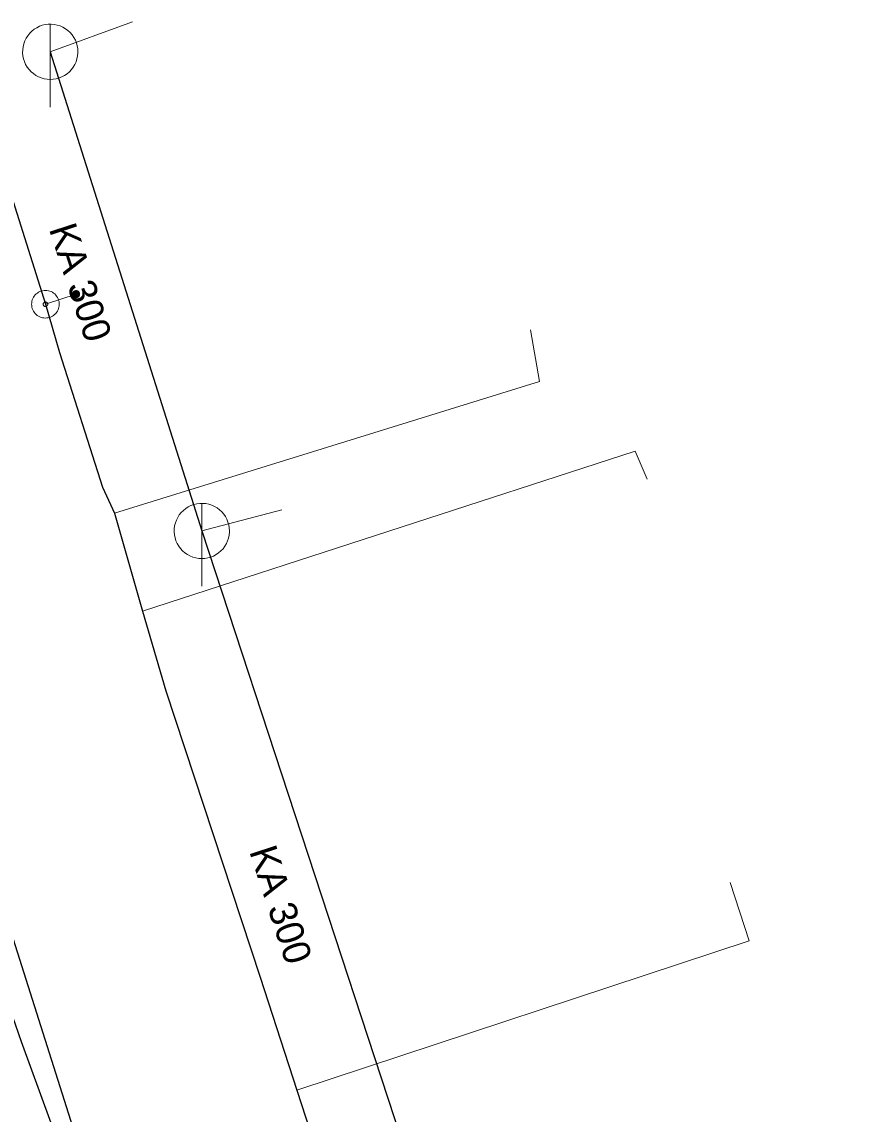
# Model space of a CAD drawing. Extents: x -807203 to -805207, y -993656 to -992505.
# Drawn here: x -807103.6 to -807072.84, y -993130.79 to -993091.29 of the extents above; entities that cross this region are included whole.
import ezdxf

# ---------------------------------------------------------------- set-up
doc = ezdxf.new("R2010")
doc.units = 0
doc.header["$LTSCALE"] = 0.4
for name, color, linetype, lineweight in [('1', 7, 'Continuous', 13), ('11', 7, 'Continuous', 13), ('13', 7, 'Continuous', 13), ('14', 7, 'Continuous', 25), ('17', 7, 'Continuous', 25), ('22', 7, 'Continuous', 13), ('47', 7, 'Continuous', 13), ('9', 7, 'Continuous', 13)]:
    doc.layers.add(name, color=color, linetype=linetype, lineweight=lineweight)

msp = doc.modelspace()

# ---------------------------------------------------------------- linework, layer by layer
at = {"layer": '11'}
for p, q in [((-807099.6, -993091.287), (-807102.57, -993092.37)), ((-807094.193, -993108.938), (-807097.09, -993109.699))]:
    msp.add_line(p, q, dxfattribs=at)
at = {"layer": '13'}
for points in [[(-807100.244, -993109.059), (-807084.873, -993104.294), (-807085.199, -993102.421)], [(-807099.235, -993112.603), (-807081.415, -993106.811), (-807080.985, -993107.831)], [(-807093.654, -993129.924), (-807077.287, -993124.524), (-807077.982, -993122.408)]]:
    msp.add_lwpolyline(points, dxfattribs=at)
at = {"layer": '14'}
for p, q in [((-807102.57, -993092.37), (-807097.09, -993109.699)), ((-807097.09, -993109.699), (-807088.03, -993137.32))]:
    msp.add_line(p, q, dxfattribs=at)
at = {"layer": '14', "lineweight": 13}
msp.add_line((-807102.744, -993101.5), (-807101.634, -993101.133), dxfattribs=at)
at = {"layer": '14'}
msp.add_lwpolyline([(-807110.309, -993104.32), (-807109.321, -993107.433), (-807106.151, -993117.421), (-807099.532, -993138.273), (-807098.539, -993141.399)], dxfattribs=at)
at = {"layer": '17'}
msp.add_line((-807104.484, -993096.025), (-807102.744, -993101.5), dxfattribs=at)
for points in [[(-807102.744, -993101.5), (-807102.241, -993103.247), (-807100.675, -993108.116), (-807100.243, -993109.059), (-807099.234, -993112.603), (-807098.39, -993115.482), (-807094.98, -993125.833), (-807093.653, -993129.923), (-807088.842, -993144.708), (-807087.517, -993148.8), (-807087.074, -993150.114), (-807085.368, -993155.225), (-807083.942, -993159.686), (-807072.827, -993193.081), (-807070.855, -993198.727), (-807058.136, -993236.557), (-807055.798, -993243.556), (-807050.671, -993258.89), (-807046.204, -993272.388), (-807040.605, -993289.576), (-807026.284, -993334.262)], [(-807106.216, -993120.722), (-807103.627, -993128.16), (-807102.219, -993132), (-807096.589, -993150.385), (-807096.195, -993151.629), (-807092.921, -993162.153), (-807079.791, -993202.059), (-807064.89, -993246.39), (-807059.596, -993262.052), (-807055.035, -993275.397), (-807053.806, -993278.989)]]:
    msp.add_lwpolyline(points, dxfattribs=at)
at = {"layer": '22'}
for p, q in [((-807102.57, -993094.37), (-807102.569, -993091.37)), ((-807097.09, -993111.699), (-807097.089, -993108.699))]:
    msp.add_line(p, q, dxfattribs=at)
for points in [[(-807101.57, -993092.37), (-807101.575, -993092.261), (-807101.593, -993092.153), (-807101.623, -993092.047), (-807101.663, -993091.946), (-807101.715, -993091.849), (-807101.777, -993091.759), (-807101.849, -993091.676), (-807101.929, -993091.602), (-807102.017, -993091.536), (-807102.111, -993091.481), (-807102.211, -993091.436), (-807102.316, -993091.403), (-807102.423, -993091.381), (-807102.532, -993091.371), (-807102.642, -993091.373), (-807102.75, -993091.387), (-807102.857, -993091.412), (-807102.96, -993091.449), (-807103.058, -993091.498), (-807103.15, -993091.556), (-807103.236, -993091.625), (-807103.313, -993091.702), (-807103.382, -993091.788), (-807103.441, -993091.88), (-807103.489, -993091.978), (-807103.526, -993092.081), (-807103.552, -993092.188), (-807103.566, -993092.296), (-807103.569, -993092.406), (-807103.559, -993092.515), (-807103.538, -993092.622), (-807103.504, -993092.726), (-807103.46, -993092.826), (-807103.405, -993092.921), (-807103.339, -993093.009), (-807103.265, -993093.089), (-807103.182, -993093.161), (-807103.092, -993093.223), (-807102.996, -993093.275), (-807102.894, -993093.316), (-807102.789, -993093.346), (-807102.681, -993093.364), (-807102.571, -993093.37), (-807102.462, -993093.364), (-807102.354, -993093.346), (-807102.249, -993093.317), (-807102.147, -993093.276), (-807102.05, -993093.224), (-807101.96, -993093.162), (-807101.877, -993093.091), (-807101.802, -993093.011), (-807101.737, -993092.923), (-807101.681, -993092.829), (-807101.637, -993092.729), (-807101.603, -993092.625), (-807101.581, -993092.517), (-807101.571, -993092.408)], [(-807096.09, -993109.699), (-807096.095, -993109.59), (-807096.113, -993109.482), (-807096.143, -993109.376), (-807096.183, -993109.275), (-807096.235, -993109.178), (-807096.297, -993109.088), (-807096.369, -993109.005), (-807096.449, -993108.931), (-807096.537, -993108.865), (-807096.631, -993108.81), (-807096.731, -993108.765), (-807096.836, -993108.732), (-807096.943, -993108.71), (-807097.052, -993108.7), (-807097.162, -993108.702), (-807097.27, -993108.716), (-807097.377, -993108.741), (-807097.48, -993108.778), (-807097.578, -993108.827), (-807097.67, -993108.885), (-807097.756, -993108.954), (-807097.833, -993109.031), (-807097.902, -993109.117), (-807097.961, -993109.209), (-807098.009, -993109.307), (-807098.046, -993109.41), (-807098.072, -993109.517), (-807098.086, -993109.625), (-807098.089, -993109.735), (-807098.079, -993109.844), (-807098.058, -993109.951), (-807098.024, -993110.055), (-807097.98, -993110.155), (-807097.925, -993110.25), (-807097.859, -993110.338), (-807097.785, -993110.418), (-807097.702, -993110.49), (-807097.612, -993110.552), (-807097.516, -993110.604), (-807097.414, -993110.645), (-807097.309, -993110.675), (-807097.201, -993110.693), (-807097.091, -993110.699), (-807096.982, -993110.693), (-807096.874, -993110.675), (-807096.769, -993110.646), (-807096.667, -993110.605), (-807096.57, -993110.553), (-807096.48, -993110.491), (-807096.397, -993110.42), (-807096.322, -993110.34), (-807096.257, -993110.252), (-807096.201, -993110.158), (-807096.157, -993110.058), (-807096.123, -993109.954), (-807096.101, -993109.846), (-807096.091, -993109.737)]]:
    msp.add_lwpolyline(points, close=True, dxfattribs=at)
at = {"layer": '47'}
for points in [[(-807102.591, -993101.976), (-807102.542, -993101.957), (-807102.495, -993101.933), (-807102.452, -993101.905), (-807102.411, -993101.873), (-807102.373, -993101.835), (-807102.34, -993101.794), (-807102.312, -993101.751), (-807102.288, -993101.704), (-807102.269, -993101.656), (-807102.255, -993101.605), (-807102.246, -993101.553), (-807102.244, -993101.501), (-807102.246, -993101.449), (-807102.254, -993101.397), (-807102.267, -993101.347), (-807102.286, -993101.298), (-807102.31, -993101.251), (-807102.339, -993101.207), (-807102.37, -993101.167), (-807102.408, -993101.129), (-807102.449, -993101.096), (-807102.493, -993101.067), (-807102.539, -993101.043), (-807102.587, -993101.024), (-807102.638, -993101.011), (-807102.69, -993101.002), (-807102.742, -993100.999), (-807102.794, -993101.002), (-807102.846, -993101.01), (-807102.896, -993101.023), (-807102.945, -993101.042), (-807102.992, -993101.066), (-807103.036, -993101.094), (-807103.076, -993101.126), (-807103.114, -993101.164), (-807103.147, -993101.204), (-807103.176, -993101.248), (-807103.2, -993101.294), (-807103.219, -993101.343), (-807103.232, -993101.394), (-807103.241, -993101.446), (-807103.244, -993101.497), (-807103.241, -993101.55), (-807103.233, -993101.602), (-807103.22, -993101.652), (-807103.201, -993101.701), (-807103.177, -993101.748), (-807103.15, -993101.792), (-807103.117, -993101.832), (-807103.079, -993101.87), (-807103.039, -993101.903), (-807102.996, -993101.931), (-807102.949, -993101.955), (-807102.9, -993101.974), (-807102.849, -993101.988), (-807102.797, -993101.997), (-807102.746, -993101.999), (-807102.693, -993101.997), (-807102.641, -993101.989)], [(-807102.718, -993101.578), (-807102.71, -993101.575), (-807102.703, -993101.57), (-807102.696, -993101.566), (-807102.689, -993101.561), (-807102.683, -993101.555), (-807102.678, -993101.548), (-807102.672, -993101.541), (-807102.669, -993101.533), (-807102.666, -993101.525), (-807102.663, -993101.517), (-807102.662, -993101.508), (-807102.662, -993101.499), (-807102.662, -993101.491), (-807102.663, -993101.483), (-807102.665, -993101.474), (-807102.668, -993101.466), (-807102.673, -993101.459), (-807102.677, -993101.452), (-807102.682, -993101.445), (-807102.688, -993101.439), (-807102.695, -993101.434), (-807102.702, -993101.428), (-807102.71, -993101.425), (-807102.718, -993101.421), (-807102.726, -993101.419), (-807102.735, -993101.418), (-807102.744, -993101.418), (-807102.752, -993101.418), (-807102.76, -993101.419), (-807102.769, -993101.421), (-807102.777, -993101.424), (-807102.784, -993101.429), (-807102.791, -993101.433), (-807102.798, -993101.438), (-807102.804, -993101.444), (-807102.81, -993101.45), (-807102.815, -993101.458), (-807102.818, -993101.466), (-807102.822, -993101.474), (-807102.824, -993101.482), (-807102.825, -993101.491), (-807102.825, -993101.5), (-807102.825, -993101.508), (-807102.824, -993101.516), (-807102.822, -993101.525), (-807102.819, -993101.533), (-807102.814, -993101.54), (-807102.81, -993101.547), (-807102.805, -993101.554), (-807102.799, -993101.56), (-807102.793, -993101.566), (-807102.785, -993101.571), (-807102.777, -993101.574), (-807102.769, -993101.577), (-807102.761, -993101.58), (-807102.752, -993101.581), (-807102.743, -993101.581), (-807102.735, -993101.581), (-807102.727, -993101.58)]]:
    msp.add_lwpolyline(points, close=True, dxfattribs=at)
at = {"layer": '9'}
for points in [[(-807101.76, -993101.133), (-807101.76, -993101.146), (-807101.757, -993101.159), (-807101.755, -993101.172), (-807101.75, -993101.184), (-807101.744, -993101.196), (-807101.737, -993101.207), (-807101.728, -993101.217), (-807101.718, -993101.227), (-807101.708, -993101.235), (-807101.698, -993101.242), (-807101.686, -993101.248), (-807101.674, -993101.253), (-807101.661, -993101.256), (-807101.647, -993101.258), (-807101.635, -993101.26), (-807101.622, -993101.259), (-807101.608, -993101.257), (-807101.596, -993101.254), (-807101.583, -993101.249), (-807101.571, -993101.243), (-807101.561, -993101.236), (-807101.551, -993101.228), (-807101.541, -993101.218), (-807101.532, -993101.208), (-807101.526, -993101.197), (-807101.52, -993101.185), (-807101.515, -993101.173), (-807101.512, -993101.16), (-807101.51, -993101.147), (-807101.507, -993101.134), (-807101.509, -993101.121), (-807101.511, -993101.108), (-807101.514, -993101.095), (-807101.519, -993101.083), (-807101.524, -993101.071), (-807101.532, -993101.06), (-807101.539, -993101.05), (-807101.549, -993101.04), (-807101.559, -993101.032), (-807101.571, -993101.025), (-807101.583, -993101.019), (-807101.595, -993101.014), (-807101.608, -993101.011), (-807101.62, -993101.009), (-807101.634, -993101.008), (-807101.647, -993101.008), (-807101.659, -993101.01), (-807101.673, -993101.013), (-807101.684, -993101.018), (-807101.696, -993101.024), (-807101.708, -993101.031), (-807101.718, -993101.039), (-807101.728, -993101.049), (-807101.735, -993101.059), (-807101.743, -993101.07), (-807101.749, -993101.082), (-807101.754, -993101.094), (-807101.757, -993101.107), (-807101.759, -993101.12)], [(-807101.74, -993101.133), (-807101.74, -993101.144), (-807101.739, -993101.155), (-807101.735, -993101.166), (-807101.732, -993101.176), (-807101.727, -993101.186), (-807101.721, -993101.195), (-807101.713, -993101.204), (-807101.706, -993101.212), (-807101.696, -993101.219), (-807101.688, -993101.225), (-807101.678, -993101.23), (-807101.668, -993101.234), (-807101.657, -993101.237), (-807101.646, -993101.24), (-807101.635, -993101.24), (-807101.624, -993101.24), (-807101.613, -993101.238), (-807101.602, -993101.235), (-807101.592, -993101.231), (-807101.581, -993101.226), (-807101.573, -993101.22), (-807101.564, -993101.213), (-807101.556, -993101.205), (-807101.549, -993101.196), (-807101.543, -993101.187), (-807101.538, -993101.177), (-807101.534, -993101.167), (-807101.531, -993101.156), (-807101.529, -993101.145), (-807101.527, -993101.134), (-807101.527, -993101.123), (-807101.529, -993101.112), (-807101.532, -993101.101), (-807101.537, -993101.091), (-807101.542, -993101.081), (-807101.548, -993101.072), (-807101.554, -993101.063), (-807101.563, -993101.055), (-807101.571, -993101.048), (-807101.581, -993101.042), (-807101.591, -993101.037), (-807101.6, -993101.033), (-807101.612, -993101.03), (-807101.622, -993101.028), (-807101.634, -993101.028), (-807101.645, -993101.027), (-807101.656, -993101.029), (-807101.667, -993101.032), (-807101.676, -993101.036), (-807101.686, -993101.041), (-807101.696, -993101.047), (-807101.705, -993101.054), (-807101.713, -993101.062), (-807101.72, -993101.071), (-807101.725, -993101.08), (-807101.73, -993101.09), (-807101.735, -993101.1), (-807101.738, -993101.111), (-807101.74, -993101.122)], [(-807101.721, -993101.133), (-807101.721, -993101.142), (-807101.72, -993101.151), (-807101.717, -993101.16), (-807101.713, -993101.168), (-807101.71, -993101.176), (-807101.705, -993101.184), (-807101.698, -993101.191), (-807101.693, -993101.197), (-807101.686, -993101.203), (-807101.678, -993101.208), (-807101.669, -993101.212), (-807101.662, -993101.215), (-807101.652, -993101.218), (-807101.644, -993101.219), (-807101.635, -993101.221), (-807101.625, -993101.22), (-807101.617, -993101.219), (-807101.608, -993101.216), (-807101.6, -993101.213), (-807101.592, -993101.209), (-807101.583, -993101.204), (-807101.576, -993101.198), (-807101.571, -993101.192), (-807101.565, -993101.185), (-807101.559, -993101.177), (-807101.556, -993101.169), (-807101.553, -993101.161), (-807101.549, -993101.152), (-807101.549, -993101.143), (-807101.546, -993101.134), (-807101.548, -993101.125), (-807101.549, -993101.116), (-807101.551, -993101.107), (-807101.554, -993101.099), (-807101.559, -993101.091), (-807101.564, -993101.083), (-807101.57, -993101.076), (-807101.576, -993101.07), (-807101.583, -993101.064), (-807101.591, -993101.059), (-807101.598, -993101.055), (-807101.607, -993101.052), (-807101.615, -993101.049), (-807101.625, -993101.048), (-807101.634, -993101.047), (-807101.642, -993101.047), (-807101.652, -993101.048), (-807101.661, -993101.051), (-807101.669, -993101.054), (-807101.676, -993101.058), (-807101.684, -993101.063), (-807101.691, -993101.069), (-807101.698, -993101.075), (-807101.703, -993101.082), (-807101.708, -993101.09), (-807101.713, -993101.098), (-807101.716, -993101.106), (-807101.718, -993101.115), (-807101.72, -993101.124)], [(-807101.701, -993101.133), (-807101.701, -993101.14), (-807101.7, -993101.147), (-807101.698, -993101.154), (-807101.696, -993101.16), (-807101.693, -993101.166), (-807101.689, -993101.172), (-807101.684, -993101.178), (-807101.679, -993101.183), (-807101.674, -993101.187), (-807101.668, -993101.191), (-807101.662, -993101.194), (-807101.656, -993101.197), (-807101.649, -993101.198), (-807101.642, -993101.201), (-807101.635, -993101.201), (-807101.627, -993101.201), (-807101.62, -993101.199), (-807101.614, -993101.198), (-807101.608, -993101.195), (-807101.6, -993101.192), (-807101.596, -993101.188), (-807101.59, -993101.184), (-807101.585, -993101.179), (-807101.581, -993101.173), (-807101.576, -993101.167), (-807101.573, -993101.161), (-807101.571, -993101.155), (-807101.569, -993101.148), (-807101.568, -993101.141), (-807101.566, -993101.134), (-807101.566, -993101.127), (-807101.568, -993101.12), (-807101.57, -993101.113), (-807101.573, -993101.107), (-807101.576, -993101.1), (-807101.58, -993101.095), (-807101.583, -993101.089), (-807101.588, -993101.084), (-807101.595, -993101.08), (-807101.6, -993101.076), (-807101.607, -993101.073), (-807101.613, -993101.07), (-807101.62, -993101.068), (-807101.627, -993101.067), (-807101.634, -993101.067), (-807101.641, -993101.067), (-807101.647, -993101.067), (-807101.654, -993101.069), (-807101.661, -993101.072), (-807101.667, -993101.075), (-807101.673, -993101.079), (-807101.679, -993101.083), (-807101.684, -993101.088), (-807101.688, -993101.094), (-807101.691, -993101.099), (-807101.695, -993101.106), (-807101.698, -993101.112), (-807101.698, -993101.119), (-807101.701, -993101.126)], [(-807101.681, -993101.133), (-807101.681, -993101.138), (-807101.681, -993101.143), (-807101.679, -993101.148), (-807101.678, -993101.152), (-807101.676, -993101.157), (-807101.673, -993101.161), (-807101.669, -993101.164), (-807101.666, -993101.168), (-807101.663, -993101.171), (-807101.659, -993101.174), (-807101.654, -993101.176), (-807101.649, -993101.178), (-807101.645, -993101.179), (-807101.64, -993101.181), (-807101.635, -993101.181), (-807101.63, -993101.181), (-807101.625, -993101.18), (-807101.62, -993101.179), (-807101.615, -993101.177), (-807101.61, -993101.175), (-807101.607, -993101.172), (-807101.603, -993101.169), (-807101.6, -993101.165), (-807101.597, -993101.162), (-807101.593, -993101.158), (-807101.592, -993101.153), (-807101.59, -993101.149), (-807101.588, -993101.144), (-807101.588, -993101.139), (-807101.587, -993101.134), (-807101.587, -993101.129), (-807101.588, -993101.124), (-807101.588, -993101.119), (-807101.591, -993101.115), (-807101.593, -993101.11), (-807101.596, -993101.106), (-807101.598, -993101.102), (-807101.602, -993101.099), (-807101.605, -993101.096), (-807101.61, -993101.093), (-807101.615, -993101.091), (-807101.619, -993101.089), (-807101.624, -993101.088), (-807101.629, -993101.087), (-807101.634, -993101.087), (-807101.639, -993101.087), (-807101.644, -993101.088), (-807101.649, -993101.088), (-807101.652, -993101.09), (-807101.657, -993101.092), (-807101.662, -993101.095), (-807101.664, -993101.098), (-807101.669, -993101.101), (-807101.671, -993101.105), (-807101.674, -993101.109), (-807101.676, -993101.114), (-807101.679, -993101.118), (-807101.679, -993101.123), (-807101.681, -993101.128)], [(-807101.661, -993101.133), (-807101.661, -993101.136), (-807101.662, -993101.139), (-807101.661, -993101.141), (-807101.659, -993101.144), (-807101.659, -993101.147), (-807101.657, -993101.149), (-807101.654, -993101.151), (-807101.652, -993101.153), (-807101.651, -993101.155), (-807101.649, -993101.157), (-807101.646, -993101.159), (-807101.642, -993101.16), (-807101.641, -993101.16), (-807101.637, -993101.161), (-807101.635, -993101.161), (-807101.632, -993101.161), (-807101.629, -993101.161), (-807101.625, -993101.16), (-807101.624, -993101.159), (-807101.62, -993101.158), (-807101.619, -993101.156), (-807101.615, -993101.154), (-807101.614, -993101.152), (-807101.613, -993101.15), (-807101.61, -993101.148), (-807101.61, -993101.145), (-807101.608, -993101.142), (-807101.608, -993101.14), (-807101.607, -993101.137), (-807101.605, -993101.134), (-807101.607, -993101.131), (-807101.607, -993101.128), (-807101.608, -993101.125), (-807101.608, -993101.123), (-807101.61, -993101.12), (-807101.612, -993101.118), (-807101.613, -993101.115), (-807101.615, -993101.113), (-807101.618, -993101.112), (-807101.62, -993101.11), (-807101.622, -993101.109), (-807101.625, -993101.108), (-807101.627, -993101.107), (-807101.63, -993101.107), (-807101.634, -993101.106), (-807101.637, -993101.107), (-807101.64, -993101.106), (-807101.642, -993101.108), (-807101.645, -993101.108), (-807101.647, -993101.109), (-807101.649, -993101.111), (-807101.652, -993101.112), (-807101.654, -993101.114), (-807101.656, -993101.117), (-807101.657, -993101.119), (-807101.659, -993101.122), (-807101.659, -993101.124), (-807101.661, -993101.127), (-807101.661, -993101.13)], [(-807101.642, -993101.133), (-807101.642, -993101.135), (-807101.642, -993101.135), (-807101.641, -993101.135), (-807101.641, -993101.137), (-807101.642, -993101.138), (-807101.64, -993101.138), (-807101.64, -993101.138), (-807101.64, -993101.14), (-807101.64, -993101.14), (-807101.639, -993101.141), (-807101.637, -993101.141), (-807101.637, -993101.141), (-807101.637, -993101.142), (-807101.635, -993101.142), (-807101.635, -993101.142), (-807101.634, -993101.142), (-807101.632, -993101.142), (-807101.632, -993101.141), (-807101.632, -993101.141), (-807101.63, -993101.141), (-807101.63, -993101.14), (-807101.63, -993101.14), (-807101.629, -993101.139), (-807101.629, -993101.139), (-807101.627, -993101.138), (-807101.627, -993101.137), (-807101.625, -993101.136), (-807101.625, -993101.136), (-807101.625, -993101.135), (-807101.625, -993101.134), (-807101.625, -993101.133), (-807101.625, -993101.132), (-807101.625, -993101.132), (-807101.627, -993101.131), (-807101.627, -993101.13), (-807101.627, -993101.129), (-807101.627, -993101.129), (-807101.629, -993101.128), (-807101.629, -993101.128), (-807101.63, -993101.127), (-807101.63, -993101.127), (-807101.632, -993101.126), (-807101.632, -993101.126), (-807101.632, -993101.126), (-807101.634, -993101.126), (-807101.635, -993101.126), (-807101.636, -993101.126), (-807101.636, -993101.126), (-807101.637, -993101.127), (-807101.637, -993101.126), (-807101.639, -993101.128), (-807101.639, -993101.128), (-807101.64, -993101.128), (-807101.64, -993101.128), (-807101.641, -993101.13), (-807101.641, -993101.131), (-807101.641, -993101.132), (-807101.642, -993101.132), (-807101.642, -993101.133)]]:
    msp.add_lwpolyline(points, close=True, dxfattribs=at)

# ---------------------------------------------------------------- texts
at = {"layer": '1'}
for p in [(-807102.627, -993098.772), (-807095.381, -993121.277)]:
    msp.add_text('KA 300', height=1, rotation=288, dxfattribs=at).set_placement(p)

doc.saveas('drawing.dxf')
